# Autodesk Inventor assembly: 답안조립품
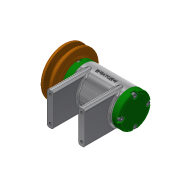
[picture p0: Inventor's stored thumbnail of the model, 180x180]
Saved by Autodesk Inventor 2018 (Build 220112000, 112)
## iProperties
Created: 2020-07
Part Number: 답안조립품
Document SubType Name: Assembly
Designer: Administrator
Author: Administrator
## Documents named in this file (15)
- C:\Users\Administrator\Desktop\700706V1039\답안조립품.iam
- C:\Users\Administrator\Desktop\700706V1039\본체.ipt
- C:\Users\Administrator\Desktop\700706V1039\축.ipt
- C:\Users\Administrator\Desktop\700706V1039\베어링 6002.ipt
- C:\Users\Administrator\Desktop\700706V1039\키 3x3x12.ipt
- C:\Users\Administrator\Desktop\700706V1039\V벨트풀리.ipt
- C:\Users\Administrator\Desktop\700706V1039\와셔 8x17.ipt
- C:\Users\Administrator\Desktop\700706V1039\스프링와셔 8.ipt
- C:\Users\Administrator\Desktop\700706V1039\너트 M8.ipt
- C:\Users\Administrator\Desktop\700706V1039\뒤커버.ipt
- C:\Users\Administrator\Desktop\700706V1039\앞커버.ipt
- C:\Users\Administrator\Desktop\700706V1039\오일 실 15 25 7.ipt
- C:\Users\Administrator\Desktop\700706V1039\볼트 M4x12.ipt
- C:\Users\Administrator\Desktop\700706V1039\와셔 6x11.5.ipt
- C:\Users\Administrator\Desktop\700706V1039\볼트 M6x8.ipt
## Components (1 placed, 1 different names)
1. V벨트풀리:1
